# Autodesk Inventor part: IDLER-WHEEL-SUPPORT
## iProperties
Created: 2007-09
Part Number: IDLER-WHEEL-SUPPORT
Material: ABS Plastic
Document SubType Name: Modeling
Density: 1.06 g/cm^3
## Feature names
1. Base1
2. Extrusion1
